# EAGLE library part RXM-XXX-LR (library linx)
LR SERIES RECEIVER MODULE Source: http://www.linxtechnologies.com .. RXM-xxx-LR_Data_Guide.pdf
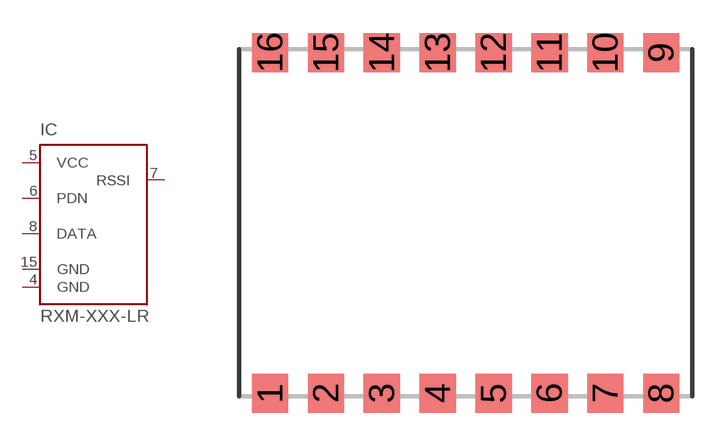
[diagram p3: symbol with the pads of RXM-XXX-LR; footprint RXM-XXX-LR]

Designator prefix IC

## RXM-XXX-LR  [RXM-XXX-LR]
4  GND  pwr
5  VCC  pwr
6  PDN  in
7  RSSI  in
8  DATA  out
15  GND  pwr

## Footprint RXM-XXX-LR (pad centres in mm)
RXM-xxx-LR Source: All Packages.pdf
smd 1.651 x 1.778: 1 -8.89,-7.747; 2 -6.35,-7.747; 3 -3.81,-7.747; 4 -1.27,-7.747; 5 1.27,-7.747; 6 3.81,-7.747; 7 6.35,-7.747; 8 8.89,-7.747; 9 8.89,7.747; 10 6.35,7.747; 11 3.81,7.747; 12 1.27,7.747; 13 -1.27,7.747; 14 -3.81,7.747; 15 -6.35,7.747; 16 -8.89,7.747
